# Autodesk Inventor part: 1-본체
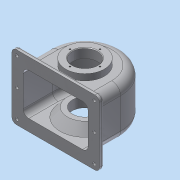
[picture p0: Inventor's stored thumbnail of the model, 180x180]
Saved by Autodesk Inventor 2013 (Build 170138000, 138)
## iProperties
Created: 2015-09
Part Number: 1-본체
Material: 알루미늄 6061
Document SubType Name: Modeling
Designer: ST4
Density: 2.71 g/cm^3
Mass: 678.469 g
Surface Area: 907.543 cm^2
Volume: 250.357 cm^3
Author: ST4
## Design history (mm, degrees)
sketch "스케치1"
  geometry: L1 (-57, -47)-(57, -47); L2 (-57, 0)-(-57, -47); L3 (57, 0)-(57, -47); A1 r 57 centre (0, 0) between (32.249, -47) and (-32.249, -47); 2 further points
  constraints: 6 end point, 4 point on circle, 2 point on line, 2 tangent, 1 centre point, 1 coincident, 1 horizontal, 1 midpoint, 1 parallel, 1 vertical, 1 vertical alignment
  dimensions: "d0" = 114 diameter of A1; "d5" = 47 distance from line of L1 point (0, 0)
extrude "돌출1" new body sketch "스케치1" stored distance "d6" = 77; taper "d7" = 0 deg
feature "쉘1" dims "d8" = 5
sketch "스케치2"
  geometry: L1 (5, -5)-(109, -5) reference; L2 (0, 0)-(114, 0) reference; L3 (0, -77)-(0, 0) reference; L4 (114, -77)-(0, -77) reference; L5 (114, -77)-(114, 0) reference; L6 (-13, 13.5)-(127, 13.5); L7 (127, 13.5)-(127, -90.5); L8 (127, -90.5)-(-13, -90.5); L9 (-13, -90.5)-(-13, 13.5); 3 further points
  constraints: 8 end point, 2 midpoint, 2 parallel, 1 horizontal, 1 horizontal alignment, 1 perpendicular, 1 vertical alignment
  dimensions: "d9" = 104 distance of L6.end L7.end; "d11" = 140 distance of L6.start L6.end
extrude "돌출2" join sketch "스케치2" distance "d12" = 7; taper "d13" = 0 deg
fillet "모깎기1" dims "d20" = 9
fillet "모깎기2" dims "d21" = 14
sketch "스케치6"
  geometry: C1 r 31 at (0, 0); A1 r 43 centre (0, 0) between (43, 0) and (-43, 0) reference
  constraints: 1 centre point, 1 coincident
  dimensions: "d32" = 62 diameter of C1
extrude "돌출3" join sketch "스케치6" distance "d34" = 10; taper "d35" = 0 deg
sketch "스케치7"
  geometry: C1 r 31 at (0, 0) reference; C2 r 20 at (0, 0)
  constraints: 1 centre point, 1 coincident
  dimensions: "d36" = 40 diameter of C2
extrude "돌출4" cut sketch "스케치7" stored distance "d38" = 10; taper "d39" = 0 deg
sketch "스케치15"
  geometry: L1 (0, -100.972)-(0, 100.972); L2 (43, -38.5)-(0, -38.5) reference; L3 (0, -33.5)-(43, -33.5) reference; L4 (-0.016, -35.5)-(36.309, -35.5); L5 (0, -19.5)-(28, -19.5); L6 (28, -19.5)-(39.747, -33.5); L7 (39.747, -33.5)-(0, -33.5); L8 (0, -33.5)-(0, -19.5); 2 further points
  constraints: 12 end point, 2 parallel, 2 point on line, 1 coincident, 1 collinear, 1 midpoint, 1 vertical
  dimensions: "d66" = 3 distance between parallel lines of L4 L2; "d71" = 56 diameter of L5.end L1; "d72" = 16 distance between parallel lines of L5 L4; "d73" = 50 deg angle of L5 L6
revolve "회전4" sketch "스케치15" stored, may be unused: angle "d74" = 90 deg
sketch "스케치16"
  geometry: L1 (43, -38.5)-(0, -38.5) reference; L2 (-40, -38.5)-(0, -38.5) reference; L3 (0, -72.766)-(0, 72.766); L4 (0, 24.5)-(0, -24.5) reference; L5 (37.416, -38.5)-(33, -33.237); L6 (0, -35.5)-(33, -35.5); L7 (28, -19.5)-(39.747, -33.5) reference; L8 (33, -35.5)-(33, -33.237); L9 (0, -38.5)-(37.416, -38.5); L10 (0, -38.5)-(0, -35.5); 2 further points
  constraints: 12 end point, 4 perpendicular, 3 point on line, 2 midpoint, 1 horizontal, 1 parallel
  dimensions: "d75" = 3 distance between parallel lines of L6 L1; "d76" = 5 distance between parallel lines of L7 L5; "d77" = 66 diameter of L8 L3
revolve "회전5" sketch "스케치16" stored, may be unused: angle "d78" = 90 deg
sketch "스케치17"
  geometry: C1 r 33 at (0, 0) reference; C2 r 20 at (0, 0)
  constraints: 1 centre point, 1 coincident
  dimensions: "d79" = 40 diameter of C2
extrude "돌출7" cut sketch "스케치17" distance "d81" = 16; taper "d82" = 0 deg
node "작업 평면2"
sketch "스케치18"
  geometry: C1 r 6 at (0, 0); 1 further point
  constraints: 1 centre point, 1 coincident
  dimensions: "d84" = 12 diameter of C1
extrude "돌출8" join sketch "스케치18" stored distance "d86" = 16; taper "d87" = 10 deg
sketch "스케치19"
  geometry: C1 r 6 at (0, 0) reference; 1 further point
  constraints: 1 coincident
hole "구멍1" sketch "스케치19" at (0, 0) diameter "d88" = 4.459; stored, may be unused: countersink angle "d92" = 90 deg, drill point angle "d94" = 118 deg; dims "d89" = 6, "d90" = 4, "d91" = 2, "d93" = 8
fillet "모깎기3" dims "d95" = 3
sketch "스케치20"
  geometry: C1 r 2.5 at (119, 82.5); C2 r 2.5 at (-5, 82.5); C3 r 2.5 at (-5, 38.5); C4 r 2.5 at (119, 38.5); C5 r 2.5 at (119, -5.5); C6 r 2.5 at (-5, -5.5); 1 further point
  constraints: 6 centre point, 5 equal radius, 4 horizontal alignment, 4 vertical alignment
  dimensions: "d96" = 44 distance of C4.centre C1.centre; "d99" = 124 distance of C1.centre C2.centre; "d100" = 62 horizontal distance of point (57, 38.5) C2.centre; "d102" = 44 distance of C5.centre C4.centre; "d103" = 5 diameter of C4
extrude "돌출9" cut sketch "스케치20" stored distance "d104" = 16; taper "d105" = 0 deg
sketch "스케치21"
  geometry: C1 r 20 at (0, 0) reference; 1 further point
  constraints: 1 vertical alignment
  dimensions: "d106" = 24 distance of C1.centre point (0, 24)
hole "구멍2" sketch "스케치21" at (0, 24) diameter "d107" = 2.459; stored, may be unused: countersink angle "d111" = 90 deg, drill point angle "d113" = 118 deg; dims "d108" = 6, "d109" = 4, "d110" = 2, "d112" = 8
sketch "스케치22"
  geometry: C1 r 20 at (0, 0) reference; 1 further point
  constraints: 1 vertical alignment
  dimensions: "d117" = 28 distance of C1.centre point (0, 28)
hole "구멍3" sketch "스케치22" at (0, 28) diameter "d118" = 2.459; stored, may be unused: countersink angle "d122" = 90 deg, drill point angle "d124" = 118 deg; dims "d119" = 7, "d120" = 4, "d121" = 2, "d123" = 9
sketch "스케치23"
  geometry: L1 (0, 40)-(-49, 40) reference; L2 (-76.5, -7)-(27.5, -7) reference; 3 further points
  constraints: 1 midpoint, 1 vertical alignment, 1 other
  dimensions: "d128" = 30 distance from line of L2 point (-24.5, 23)
feature "엠보싱1" sketch "스케치23" dims "d0" = 114, "d5" = 47, "d9" = 104, "d11" = 140, "d129" = 0.5, "d130" = 0
fillet "모깎기4" dims "d131" = 1
fillet "모깎기5" dims "d132" = 7
chamfer "모따기1" distance "d133" = 1; stored, may be unused: second distance "d134" = 2, angle "d135" = 45 deg
fillet "모깎기6" dims "d136" = 0.5
fillet "모깎기7" dims "d137" = 3
fillet "모깎기8" dims "d138" = 3
node "솔리드1"
pattern_circular "원형 패턴1" dims angle "d115" = 360 deg
pattern_circular "원형 패턴2" dims angle "d126" = 360 deg
other parameters: "d51" = 66, "d83" = 63
